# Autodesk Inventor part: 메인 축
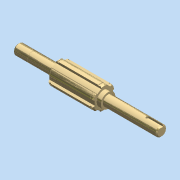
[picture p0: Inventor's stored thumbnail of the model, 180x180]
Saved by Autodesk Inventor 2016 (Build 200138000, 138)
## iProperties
Created: 2015-11
Part Number: 메인 축
Document SubType Name: 모델링
Designer: mdu
Mass: 168.566 g
Surface Area: 72.5104 cm^2
Volume: 21.4461 cm^3
Density: 7.86 g/cm^3
Material: 강철, 연강
Appearance: 강철
변환 표준: STEP AP214IS
파일 이름: C:\Users\SeoGD\Desktop\?쒗뿕\硫붿씤 異?.stp
전처리기: Build: 253, Release: 2010 SP1 - Date: Wed 07/29/2009
전송 단위: 밀리미터
불확실성: 0.01
Author: mdu
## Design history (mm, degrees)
sketch "스케치1"
  geometry: L1 (-69.5, 0)-(69.5, 0); L2 (69.5, 0)-(69.5, 5); L3 (69.5, 5)-(55.5, 5); L4 (55.5, 5)-(55.5, 4.8); L5 (55.5, 4.8)-(54.35, 4.8); L6 (54.35, 4.8)-(54.35, 5); L7 (54.35, 5)-(30.5, 5); L8 (30.5, 5)-(30.5, 9); L9 (30.5, 9)-(-13.5, 9); L10 (-13.5, 9)-(-13.5, 7); L11 (-13.5, 7)-(-17.5, 7); L12 (-17.5, 7)-(-17.5, 5); L13 (-17.5, 5)-(-69.5, 5); L14 (-69.5, 5)-(-69.5, 0); 2 further points
  constraints: 28 end point, 9 parallel, 4 collinear, 2 perpendicular, 1 coincident, 1 horizontal, 1 midpoint
  dimensions: "d2" = 1.15 distance between parallel lines of L6 L4; "d3" = 10 diameter of L3 L1; "d4" = 9.6 diameter of L5 L1; "d6" = 44 distance between parallel lines of L10 L8; "d7" = 4 distance between parallel lines of L12 L10; "d8" = 14 diameter of L11 L1; "d9" = 18 diameter of L9 L1; "d33" = 52 distance from line of L12.end L14; "d37" = 39 distance between parallel lines of L8 L2; "d38" = 14 distance between parallel lines of L2 L4
revolve "회전1" sketch "스케치1" stored, may be unused: angle "d10" = 90 deg
sketch "스케치2"
  geometry: L1 (2.5, 10.712)-(2.5, 8.646); L2 (-2.5, 10.712)-(-2.5, 8.646); A1 r 9 centre (0, 0) between (2.5, 8.646) and (-2.5, 8.646) reference; A2 r 11 centre (0, 0) between (2.5, 10.712) and (-2.5, 10.712); 1 further point
  constraints: 4 end point, 4 point on circle, 2 parallel, 1 centre point, 1 coincident, 1 vertical
  dimensions: "d11" = 22 diameter of A2; "d12" = 5 distance between parallel lines of L1 L2
extrude "돌출1" join sketch "스케치2" stored distance "d13" = 10; taper "d14" = 0 deg
chamfer "모따기1" distance "d15" = 1; stored, may be unused: second distance "d16" = 2, angle "d17" = 45 deg
node "작업 평면1"
node "작업 평면2"
sketch "스케치3"
  geometry: L1 (2.5, 10.712)-(2.5, 10.198); L2 (-2.5, 10.712)-(-2.5, 10.198); A1 r 11 centre (0, 0) between (2.5, 10.712) and (-2.5, 10.712) reference; A2 r 10.5 centre (0, 0) between (2.5, 10.198) and (-2.5, 10.198); 1 further point
  constraints: 4 end point, 2 point on circle, 1 centre point, 1 coincident, 1 parallel, 1 vertical
  dimensions: "d19" = 21 diameter of A2
extrude "돌출2" cut sketch "스케치3" distance "d20" = 1.35; taper "d21" = 0 deg
node "작업 평면3"
sketch "스케치4"
  geometry: L1 (-26, -5)-(-26, 5) reference; L2 (-26, 1.5)-(-12.5, 1.5); L3 (-12.5, -1.5)-(-26, -1.5); A1 r 1.5 centre (-12.5, 0) between (-12.5, -1.5) and (-12.5, 1.5); 2 further points
  constraints: 4 end point, 2 perpendicular, 2 point on circle, 2 point on line, 2 tangent, 1 centre point, 1 horizontal alignment, 1 midpoint
  dimensions: "d25" = 3 distance between parallel lines of L3 L2; "d26" = 15 dimension on A1 L1
extrude "돌출3" cut sketch "스케치4" distance "d27" = 1.8; taper "d28" = 0 deg
chamfer "모따기2" distance "d29" = 1; stored, may be unused: second distance "d30" = 2, angle "d31" = 45 deg
node "솔리드1"
node "솔리드 본체"
node "곡면 본체"
mirror "대칭1"
pattern_circular "원형 패턴1" dims "d23" = 360 deg
node "솔리드2"
other parameters: "d18" = -1.65
